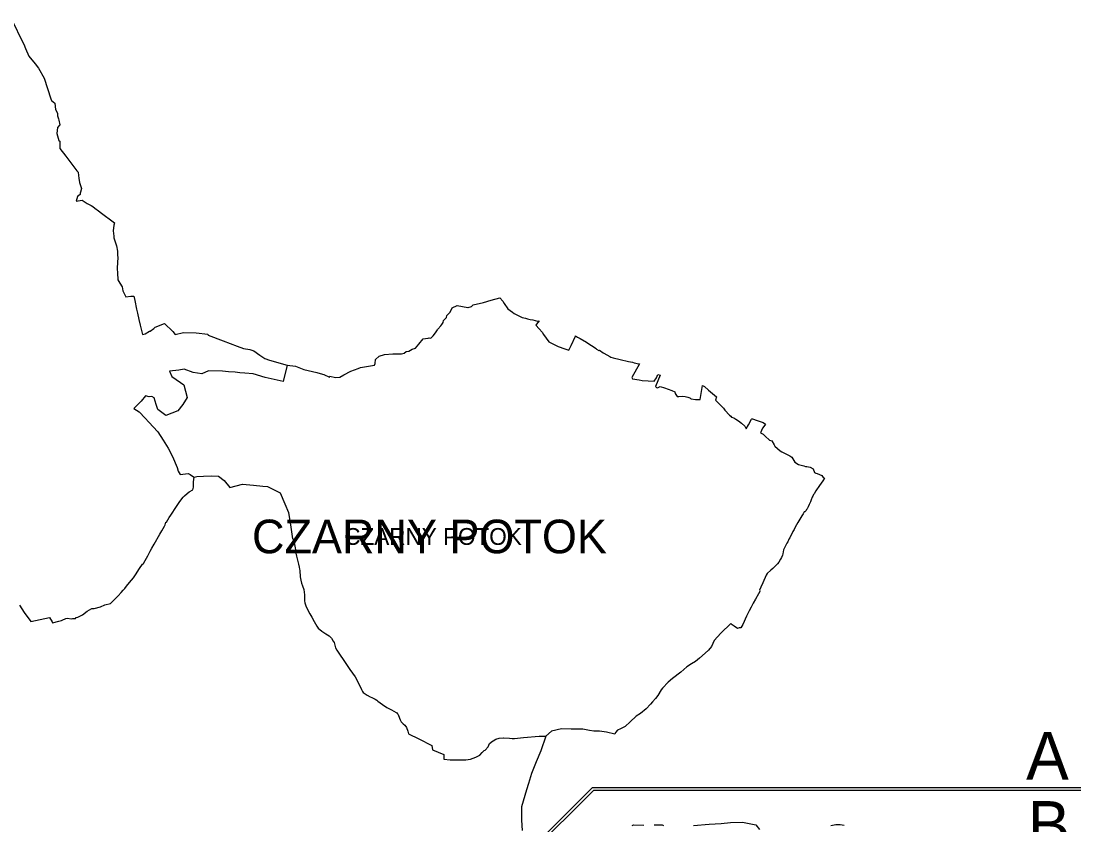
# Model space of a CAD drawing. Extents: x -562952 to -547638, y 190691 to 208158.
# Drawn here: x -557283 to -551614, y 202309 to 206612 of the extents above; entities that cross this region are included whole.
import ezdxf

# ---------------------------------------------------------------- set-up
doc = ezdxf.new("R2010")
doc.units = 0
for name, color, linetype in [('granica A_B', 7, 'Continuous'), ('granica_gminy', 7, 'Continuous'), ('granica_sołectwa', 7, 'Continuous'), ('nazwy miejscowości', 7, 'Continuous'), ('nazwy miejscowości DUŻE', 7, 'Continuous'), ('obwódka', 7, 'Continuous')]:
    doc.layers.add(name, color=color, linetype=linetype)

msp = doc.modelspace()

# ---------------------------------------------------------------- linework, layer by layer
at = {"layer": 'granica A_B'}
for points in [[(-554559.4, 202174.8), (-554225.8, 202508.4), (-551613.8, 202508.4)], [(-554557.2, 202157.2), (-554220, 202494.4), (-551613.8, 202494.4)]]:
    msp.add_lwpolyline(points, dxfattribs=at)
at = {"layer": 'granica_gminy'}
for points in [[(-557330.2, 206611.8), (-557277.5, 206504.5), (-557269.5, 206488.5), (-557259.1, 206466.4), (-557241.7, 206425), (-557208.3, 206383), (-557189.9, 206360.2), (-557159.5, 206306.4), (-557125.1, 206195.8), (-557120.8, 206186.2), (-557103.4, 206172.2), (-557100.1, 206139), (-557088, 206120), (-557088.7, 206105), (-557083.7, 206089.6), (-557080.7, 206081.2), (-557076, 206056.5), (-557089, 206043.3), (-557092.7, 206009.9), (-557081.4, 205973.4), (-557076, 205968.7), (-557075.7, 205929.6), (-557044.2, 205888.9), (-556985, 205810.3), (-556978.7, 205802.6), (-556976, 205785.3), (-556974.6, 205771.6), (-556971.3, 205748.1), (-556960.3, 205715.8), (-556965.7, 205696.4), (-556966.7, 205691.4), (-556967.3, 205684.3), (-556982.3, 205672.2), (-556988.7, 205648.3), (-556957.1, 205653.9), (-556929.1, 205636.3), (-556908.4, 205624.2), (-556899.5, 205619.8), (-556888.5, 205611.3), (-556870, 205596.1), (-556852.5, 205583.3), (-556831.1, 205567.6), (-556811.9, 205553.3), (-556784.1, 205532.5), (-556787.4, 205519.9), (-556791.3, 205489.2), (-556787.8, 205459.8), (-556786.7, 205451.4), (-556775.9, 205420.4), (-556773.7, 205408.4), (-556767.7, 205380.1), (-556767, 205358.3), (-556766.2, 205346.3), (-556769, 205290.3), (-556768, 205258.8), (-556765.9, 205233), (-556765.5, 205226.2), (-556755.2, 205209.9), (-556742.4, 205189.6), (-556739.1, 205167.3), (-556723.6, 205136.5), (-556696.6, 205138.8), (-556679.9, 205140.1), (-556675, 205115.6), (-556665.5, 205070.6), (-556660.4, 205048.5), (-556652.9, 205014.7), (-556646.6, 204984.5), (-556634.6, 204933.5), (-556619.9, 204937.6), (-556596.1, 204952.4), (-556592.3, 204952.4), (-556573.6, 204966.3), (-556566.7, 204973.4), (-556515.4, 204993.2), (-556472.2, 204950.4), (-556459.6, 204935), (-556414.7, 204945.6), (-556347.3, 204943.6), (-556284.8, 204936.3), (-556282.4, 204929.8), (-556201.9, 204900.2), (-556127.3, 204872), (-556093.3, 204859.7), (-556059.7, 204853), (-556038.7, 204846.7), (-556005.6, 204823.7), (-555978.5, 204805.4), (-555953.5, 204797), (-555859, 204770.3), (-555815.9, 204764.8), (-555771.3, 204746), (-555701.3, 204730.7), (-555683.9, 204725.4), (-555663.8, 204719.4), (-555634.2, 204706.5), (-555631.3, 204710.6), (-555601.8, 204703.6), (-555578.9, 204705.9), (-555557.5, 204718.5), (-555519.5, 204737.6), (-555479.6, 204752.5), (-555467.5, 204756.7), (-555456.4, 204758.9), (-555436.1, 204762), (-555391.7, 204769.5), (-555388.9, 204778.3), (-555386.4, 204800), (-555367.7, 204817.4), (-555339.8, 204826.7), (-555294.6, 204830), (-555247.3, 204829.9), (-555234.4, 204834.7), (-555222.7, 204843.7), (-555209.3, 204844.4), (-555190.3, 204855.1), (-555172.9, 204861.1), (-555155.7, 204882.4), (-555131.6, 204911.6), (-555108, 204914.9), (-555105.9, 204914.5), (-555100.8, 204916.2), (-555091.9, 204914.7), (-555079.2, 204926.3), (-555065.5, 204942.6), (-555055.5, 204959.8), (-555053.6, 204963.1), (-555038.4, 204981.1), (-555033, 204987.5), (-555026, 204998.8), (-555023.1, 205008.5), (-555007.3, 205025.3), (-555004.8, 205036.1), (-554988.6, 205054.2), (-554977.6, 205077.8), (-554950.7, 205088.8), (-554893.7, 205079.4), (-554891, 205079.3), (-554874.5, 205084.8), (-554865.2, 205092.6), (-554809.7, 205105.2), (-554769, 205118.6), (-554721.8, 205131), (-554706.8, 205113.4), (-554699.2, 205099.7), (-554679.3, 205071.5), (-554654.4, 205053.2), (-554644.9, 205046.4), (-554616.4, 205033), (-554603.2, 205025.4), (-554585.5, 205021.2), (-554573.2, 205018.3), (-554559, 205014.3), (-554545.1, 205012.3), (-554521, 205005.5), (-554511.3, 205008.1), (-554525.8, 204989.6), (-554529.8, 204984.9), (-554512.4, 204964.8), (-554495.9, 204946.8), (-554488.6, 204934.9), (-554459.4, 204894.2), (-554410.1, 204870.1), (-554375.1, 204858.2), (-554352.5, 204850.5), (-554339.7, 204875.4), (-554317.7, 204924.8), (-554316.9, 204926.8), (-554305.8, 204920.6), (-554291.7, 204912.4), (-554257.8, 204892.4), (-554245.8, 204884), (-554231.3, 204874.8), (-554205.9, 204859.1), (-554205.1, 204855.4), (-554192.4, 204848.6), (-554189.7, 204849.5), (-554169.9, 204836.5), (-554165, 204834), (-554134.1, 204815.5), (-554127.9, 204812.4), (-554116, 204809.2), (-554078.9, 204800.5), (-554033.4, 204789.5), (-554012.7, 204785.6), (-554002.6, 204782.9), (-553978, 204777.7), (-553974.5, 204776.5), (-554016.6, 204704.3), (-554012.2, 204697.5), (-554011.7, 204696.8), (-553976.2, 204691.6), (-553960.6, 204687.7), (-553895.6, 204685), (-553883.3, 204701.4), (-553876, 204720.7), (-553864.8, 204717.1), (-553889.9, 204656.4), (-553883.1, 204651.1), (-553878.7, 204647.9), (-553864.1, 204655), (-553841.1, 204647.9), (-553802.2, 204634.7), (-553785.1, 204626.9), (-553783.6, 204618.8), (-553772.6, 204602.4), (-553764.6, 204603.1), (-553742.5, 204604.1), (-553730, 204602.2), (-553716.8, 204598.8), (-553706, 204595.6), (-553701.9, 204591.4), (-553699.2, 204590.5), (-553674.5, 204585.3), (-553650.5, 204586.8), (-553637.6, 204660.7), (-553627.9, 204655.5), (-553606, 204636.3), (-553563.6, 204600.2), (-553567.6, 204581.9), (-553555, 204570.6), (-553536.4, 204551.1), (-553524.9, 204539.2), (-553518.2, 204529.4), (-553493, 204502.8), (-553487, 204496.3), (-553482, 204492.2), (-553469.7, 204487.8), (-553460, 204481.5), (-553445, 204471.4), (-553429.5, 204459.1), (-553411.2, 204444), (-553404.7, 204429.6), (-553392.4, 204451.1), (-553376.3, 204481), (-553373.3, 204482.8), (-553369.8, 204482.5), (-553344.7, 204473.8), (-553313.9, 204463.3), (-553300.9, 204453.2), (-553309.2, 204441.7), (-553316.1, 204432.1), (-553327.8, 204407.6), (-553312.5, 204399.7), (-553301.7, 204389.6), (-553280.1, 204369.2), (-553267.6, 204364.7), (-553255, 204343.4), (-553250.9, 204336.6), (-553221.8, 204311.7), (-553212.8, 204306.5), (-553187.6, 204292.6), (-553171.4, 204284.3), (-553159.3, 204277.8), (-553143.1, 204249.9), (-553124.6, 204238.5), (-553096.5, 204231.3), (-553086.4, 204227.8), (-553079.6, 204227), (-553061.2, 204224.5), (-553045.5, 204215.4), (-553037.9, 204195.2), (-553031.2, 204191.4), (-553023.7, 204189.6), (-552999.9, 204179.7), (-552992.7, 204168.5), (-552985.3, 204164.4), (-552994.5, 204150.9), (-553002.9, 204138.2), (-553011.7, 204125.6), (-553031.4, 204096.4), (-553040.9, 204081.3), (-553043.4, 204077.2), (-553047.5, 204069), (-553050.6, 204062.9), (-553057.2, 204048.2), (-553058.6, 204044.1), (-553060.8, 204039.1), (-553067.1, 204024.3), (-553072.9, 204011.8), (-553078.3, 204001.5), (-553080.8, 203997.2), (-553083.8, 203991.5), (-553087.5, 203987.5), (-553090.4, 203985.5), (-553094.1, 203983.9), (-553099.5, 203974.6), (-553105.7, 203963.3), (-553116.9, 203945.3), (-553127.9, 203926.7), (-553141.9, 203902.9), (-553148.2, 203890.6), (-553154.1, 203879.1), (-553155.7, 203875.1), (-553171.1, 203845.7), (-553175.7, 203837.6), (-553182, 203824.7), (-553186.5, 203816.3), (-553204, 203781.6), (-553204.6, 203780.4), (-553207.9, 203759.9), (-553210.4, 203753.4), (-553215.7, 203740.5), (-553219.7, 203730.9), (-553229.1, 203714.5), (-553236.2, 203706.8), (-553249.6, 203693.5), (-553262, 203680.6), (-553271.8, 203672.4), (-553291.2, 203654.5), (-553296.8, 203646.3), (-553315.8, 203604.2), (-553325.4, 203581.5), (-553332.1, 203564.6), (-553330.8, 203562.5), (-553331.3, 203558.1), (-553338.5, 203545.9), (-553354.2, 203516.3), (-553365.9, 203495.3), (-553377.4, 203474.9), (-553388.5, 203454.7), (-553399.3, 203432.9), (-553402.2, 203426.7), (-553422.8, 203380.8), (-553432, 203364.4), (-553441.3, 203363.8), (-553450.9, 203359.9), (-553469.1, 203373.1), (-553478.3, 203380.5), (-553487, 203386.5), (-553540.4, 203334.9), (-553574.7, 203296.1), (-553590.3, 203263.2), (-553605.2, 203244.1), (-553622.8, 203227.2), (-553653, 203201.3), (-553675.5, 203182.9), (-553697.1, 203171), (-553721.7, 203154.7), (-553754.2, 203127.1), (-553797.7, 203092.9), (-553821.3, 203072), (-553851, 203040.9), (-553859.3, 203031), (-553876.1, 203001), (-553889.1, 202985), (-553905.6, 202968.2), (-553915.3, 202954.7), (-553939.1, 202930.4), (-553969.6, 202904.7), (-553992.4, 202890.9), (-554025.3, 202860), (-554051.2, 202835.6), (-554076.6, 202822.3), (-554091.7, 202815.3), (-554103.6, 202802.6), (-554106.9, 202795), (-554151.9, 202805.8), (-554188.7, 202810.2), (-554218.8, 202811), (-554242, 202814.5), (-554277.7, 202820.2), (-554297.8, 202821.5), (-554339.6, 202820.5), (-554392.4, 202823.1), (-554445.8, 202810.5), (-554476.4, 202783.6), (-554502.2, 202705.9), (-554527.1, 202645.7), (-554552.1, 202583.8), (-554569.4, 202529.3), (-554579.5, 202496), (-554588.2, 202466.6), (-554605.7, 202405.1), (-554607, 202333.1), (-554602.3, 202278.1)], [(-554013.3, 202305), (-554007.8, 202308.9), (-553951.8, 202307.6)], [(-553896.2, 202308.1), (-553852.8, 202308.9), (-553847.1, 202305)], [(-553686.5, 202306), (-553602.2, 202312), (-553538, 202316.6), (-553487.2, 202321), (-553423.4, 202323.8), (-553352.3, 202309.4), (-553333.1, 202284.1)], [(-552950.9, 202305), (-552923.6, 202310.7), (-552900.6, 202310.9), (-552880.3, 202307.6)]]:
    msp.add_lwpolyline(points, dxfattribs=at)
at = {"layer": 'granica_sołectwa'}
for points in [[(-555860, 204770.6), (-555882.1, 204682.5), (-555977.9, 204704.1), (-556041.9, 204724.3), (-556086.4, 204727.7), (-556113.4, 204729.7), (-556138.7, 204732.4), (-556173.2, 204734.4), (-556206.6, 204738.5), (-556281.1, 204739.5), (-556316.1, 204723.3), (-556363.1, 204730), (-556410, 204748.3), (-556439.5, 204742.7), (-556489.8, 204737.5), (-556476, 204709.2), (-556453.6, 204692.8), (-556430.5, 204676.7), (-556412.3, 204664.8), (-556394.8, 204596.4), (-556417.5, 204559.1), (-556444, 204524.8), (-556509.2, 204500.2), (-556551.1, 204533.4), (-556560.8, 204558.7), (-556570.5, 204594.9), (-556583.2, 204601.6), (-556598.4, 204601.2), (-556618.2, 204606.1), (-556641.7, 204576.6), (-556679.3, 204537.1), (-556651.3, 204519.7), (-556620, 204486.2), (-556600.2, 204464.9), (-556552.2, 204412.9), (-556523.5, 204367.8), (-556497, 204324.9), (-556474, 204280.3), (-556449, 204222.5), (-556442.3, 204202.2), (-556431.5, 204184.3), (-556388.7, 204189.5), (-556378.6, 204185), (-556356.4, 204169)], [(-556361.1, 204116), (-556361.1, 204126.8), (-556361.5, 204145.3), (-556357.1, 204170.5), (-556343.1, 204174.3), (-556306.9, 204176.3), (-556265.1, 204178.2), (-556228, 204175.2), (-556197.3, 204152.3), (-556166.2, 204114.1), (-556099.1, 204132.3), (-556040.1, 204126.9), (-555990.3, 204122.3), (-555965.7, 204119.8), (-555897.2, 204085.9), (-555872.3, 204027.1), (-555851.9, 203982), (-555839.6, 203902.7), (-555838.5, 203890.2), (-555831.5, 203840.5), (-555826.7, 203838.7), (-555819.4, 203801.4), (-555814, 203772.1), (-555812.6, 203762.9), (-555810.1, 203747.2), (-555803.5, 203719.5), (-555799.2, 203704.8), (-555795.1, 203687.6), (-555793.1, 203677.3), (-555791.8, 203670.3), (-555789.9, 203636.3), (-555787.2, 203618.1), (-555783.6, 203602.7), (-555778.2, 203587.7), (-555771.4, 203568.2), (-555768.6, 203553.8), (-555767.4, 203540.4), (-555766.4, 203517.6), (-555767.1, 203508.2), (-555765, 203497.3), (-555760.4, 203482.1), (-555751.5, 203462), (-555738.3, 203439), (-555727, 203420.4), (-555715.4, 203397), (-555701.1, 203371.9), (-555693.7, 203362.6), (-555674.8, 203346.2), (-555652.5, 203331.1), (-555634.8, 203320.2), (-555622.4, 203308.4), (-555613.2, 203292.3), (-555609.2, 203285), (-555600.6, 203257.3), (-555594.9, 203244.6), (-555541.5, 203167.2)], [(-557291.4, 203484.1), (-557267.3, 203446.2), (-557230.6, 203398.3), (-557130.8, 203418.8), (-557116.6, 203395.3), (-557115.9, 203390.4), (-557081, 203399), (-557068, 203402.5), (-557063.9, 203405.5), (-557044.8, 203413.3), (-557035.5, 203415.1), (-557015.1, 203412.2), (-557007.5, 203412.8), (-556992.6, 203414), (-556987.9, 203419.1), (-556979.6, 203421.4), (-556955.1, 203434), (-556930.5, 203453.6), (-556904.9, 203466.8), (-556893.1, 203466.8), (-556858.8, 203476.6), (-556835.1, 203487), (-556805.5, 203494.3), (-556764.5, 203535.2), (-556747.8, 203552.7), (-556736.5, 203565.4), (-556728.9, 203574.5), (-556719.6, 203586), (-556703.1, 203606.1), (-556682, 203632), (-556671.7, 203646.6), (-556649.4, 203680.6), (-556633.4, 203704), (-556628.6, 203708.8), (-556620.2, 203724.9), (-556605.8, 203748.9), (-556592.2, 203773.7), (-556583.3, 203789.3), (-556570.6, 203811.3), (-556540.6, 203865.1), (-556530.1, 203883), (-556516.4, 203907.5), (-556512.8, 203915.4), (-556508.8, 203928.8), (-556505.1, 203928.5), (-556491.1, 203954.2), (-556482.5, 203967.1), (-556451.6, 204014), (-556433.6, 204039.6), (-556416.5, 204063.3), (-556409.2, 204070.2), (-556395.5, 204082.8), (-556384.1, 204091.5), (-556364.1, 204102.4), (-556361.1, 204116)], [(-555541.5, 203167.2), (-555524, 203141.1), (-555496.8, 203101.6), (-555483.1, 203078.6), (-555463, 203033.6), (-555457.3, 203022.4), (-555454.1, 203018), (-555431.9, 203003.8), (-555415.2, 202993.5), (-555406.3, 202991.1), (-555388.8, 202982.2), (-555380.2, 202976.1), (-555374.9, 202971.5), (-555350.5, 202953.4), (-555326.3, 202937.5), (-555319.7, 202933.4), (-555301.1, 202924.1), (-555276.5, 202910.6), (-555273.2, 202908.4), (-555268.8, 202903.7), (-555266.4, 202899.1), (-555259.5, 202879.8), (-555256, 202871.3), (-555249.9, 202859.8), (-555246.9, 202857.2), (-555238.6, 202849.3), (-555229.8, 202841.6), (-555222.2, 202829.4), (-555215, 202810.7), (-555209.8, 202796.8), (-555156.2, 202769.2), (-555085.3, 202733.8), (-555082.4, 202710.8), (-555021, 202684.6), (-555021.6, 202661), (-554987.6, 202657.6), (-554949.3, 202656.5), (-554904.8, 202656.9), (-554878.2, 202659.8), (-554849.7, 202671.5), (-554829.4, 202681.5), (-554815.8, 202696), (-554809.6, 202703.4), (-554805.4, 202706.4), (-554800.8, 202708.8), (-554784.3, 202725.9), (-554776.9, 202744.8), (-554761.3, 202756.6), (-554757, 202759.2), (-554743, 202767.4), (-554726.3, 202772.6), (-554703.5, 202775.3), (-554703, 202774.3), (-554669.7, 202772.6), (-554656.3, 202771.7)], [(-554656.3, 202771.7), (-554642.9, 202771.3), (-554596.3, 202776.7), (-554511.2, 202784.4), (-554476.4, 202783.6)]]:
    msp.add_lwpolyline(points, dxfattribs=at)
at = {"layer": 'obwódka'}
for points in [[(-557330.2, 206611.8), (-557277.5, 206504.5), (-557269.5, 206488.5), (-557259.1, 206466.4), (-557241.7, 206425), (-557208.3, 206383), (-557189.9, 206360.2), (-557159.5, 206306.4), (-557125.1, 206195.8), (-557120.8, 206186.2), (-557103.4, 206172.2), (-557100.1, 206139), (-557088, 206120), (-557088.7, 206105), (-557083.7, 206089.6), (-557080.7, 206081.2), (-557076, 206056.5), (-557089, 206043.3), (-557092.7, 206009.9), (-557081.4, 205973.4), (-557076, 205968.7), (-557075.7, 205929.6), (-557044.2, 205888.9), (-556985, 205810.3), (-556978.7, 205802.6), (-556976, 205785.3), (-556974.6, 205771.6), (-556971.3, 205748.1), (-556960.3, 205715.8), (-556965.7, 205696.4), (-556966.7, 205691.4), (-556967.3, 205684.3), (-556982.3, 205672.2), (-556988.7, 205648.3), (-556957.1, 205653.9), (-556929.1, 205636.3), (-556908.4, 205624.2), (-556899.5, 205619.8), (-556888.5, 205611.3), (-556870, 205596.1), (-556852.5, 205583.3), (-556831.1, 205567.6), (-556811.9, 205553.3), (-556784.1, 205532.5), (-556787.4, 205519.9), (-556791.3, 205489.2), (-556787.8, 205459.8), (-556786.7, 205451.4), (-556775.9, 205420.4), (-556773.7, 205408.4), (-556767.7, 205380.1), (-556767, 205358.3), (-556766.2, 205346.3), (-556769, 205290.3), (-556768, 205258.8), (-556765.9, 205233), (-556765.5, 205226.2), (-556755.2, 205209.9), (-556742.4, 205189.6), (-556739.1, 205167.3), (-556723.6, 205136.5), (-556696.6, 205138.8), (-556679.9, 205140.1), (-556675, 205115.6), (-556665.5, 205070.6), (-556660.4, 205048.5), (-556652.9, 205014.7), (-556646.6, 204984.5), (-556634.6, 204933.5), (-556619.9, 204937.6), (-556596.1, 204952.4), (-556592.3, 204952.4), (-556573.6, 204966.3), (-556566.7, 204973.4), (-556515.4, 204993.2), (-556472.2, 204950.4), (-556459.6, 204935), (-556414.7, 204945.6), (-556347.3, 204943.6), (-556284.8, 204936.3), (-556282.4, 204929.8), (-556201.9, 204900.2), (-556127.3, 204872), (-556093.3, 204859.7), (-556059.7, 204853), (-556038.7, 204846.7), (-556005.6, 204823.7), (-555978.5, 204805.4), (-555953.5, 204797), (-555859, 204770.3), (-555815.9, 204764.8), (-555771.3, 204746), (-555701.3, 204730.7), (-555683.9, 204725.4), (-555663.8, 204719.4), (-555634.2, 204706.5), (-555631.3, 204710.6), (-555601.8, 204703.6), (-555578.9, 204705.9), (-555557.5, 204718.5), (-555519.5, 204737.6), (-555479.6, 204752.5), (-555467.5, 204756.7), (-555456.4, 204758.9), (-555436.1, 204762), (-555391.7, 204769.5), (-555388.9, 204778.3), (-555386.4, 204800), (-555367.7, 204817.4), (-555339.8, 204826.7), (-555294.6, 204830), (-555247.3, 204829.9), (-555234.4, 204834.7), (-555222.7, 204843.7), (-555209.3, 204844.4), (-555190.3, 204855.1), (-555172.9, 204861.1), (-555155.7, 204882.4), (-555131.6, 204911.6), (-555108, 204914.9), (-555105.9, 204914.5), (-555100.8, 204916.2), (-555091.9, 204914.7), (-555079.2, 204926.3), (-555065.5, 204942.6), (-555055.5, 204959.8), (-555053.6, 204963.1), (-555038.4, 204981.1), (-555033, 204987.5), (-555026, 204998.8), (-555023.1, 205008.5), (-555007.3, 205025.3), (-555004.8, 205036.1), (-554988.6, 205054.2), (-554977.6, 205077.8), (-554950.7, 205088.8), (-554893.7, 205079.4), (-554891, 205079.3), (-554874.5, 205084.8), (-554865.2, 205092.6), (-554809.7, 205105.2), (-554769, 205118.6), (-554721.8, 205131), (-554706.8, 205113.4), (-554699.2, 205099.7), (-554679.3, 205071.5), (-554654.4, 205053.2), (-554644.9, 205046.4), (-554616.4, 205033), (-554603.2, 205025.4), (-554585.5, 205021.2), (-554573.2, 205018.3), (-554559, 205014.3), (-554545.1, 205012.3), (-554521, 205005.5), (-554511.3, 205008.1), (-554525.8, 204989.6), (-554529.8, 204984.9), (-554512.4, 204964.8), (-554495.9, 204946.8), (-554488.6, 204934.9), (-554459.4, 204894.2), (-554410.1, 204870.1), (-554375.1, 204858.2), (-554352.5, 204850.5), (-554339.7, 204875.4), (-554317.7, 204924.8), (-554316.9, 204926.8), (-554305.8, 204920.6), (-554291.7, 204912.4), (-554257.8, 204892.4), (-554245.8, 204884), (-554231.3, 204874.8), (-554205.9, 204859.1), (-554205.1, 204855.4), (-554192.4, 204848.6), (-554189.7, 204849.5), (-554169.9, 204836.5), (-554165, 204834), (-554134.1, 204815.5), (-554127.9, 204812.4), (-554116, 204809.2), (-554078.9, 204800.5), (-554033.4, 204789.5), (-554012.7, 204785.6), (-554002.6, 204782.9), (-553978, 204777.7), (-553974.5, 204776.5), (-554016.6, 204704.3), (-554012.2, 204697.5), (-554011.7, 204696.8), (-553976.2, 204691.6), (-553960.6, 204687.7), (-553895.6, 204685), (-553883.3, 204701.4), (-553876, 204720.7), (-553864.8, 204717.1), (-553889.9, 204656.4), (-553883.1, 204651.1), (-553878.7, 204647.9), (-553864.1, 204655), (-553841.1, 204647.9), (-553802.2, 204634.7), (-553785.1, 204626.9), (-553783.6, 204618.8), (-553772.6, 204602.4), (-553764.6, 204603.1), (-553742.5, 204604.1), (-553730, 204602.2), (-553716.8, 204598.8), (-553706, 204595.6), (-553701.9, 204591.4), (-553699.2, 204590.5), (-553674.5, 204585.3), (-553650.5, 204586.8), (-553637.6, 204660.7), (-553627.9, 204655.5), (-553606, 204636.3), (-553563.6, 204600.2), (-553567.6, 204581.9), (-553555, 204570.6), (-553536.4, 204551.1), (-553524.9, 204539.2), (-553518.2, 204529.4), (-553493, 204502.8), (-553487, 204496.3), (-553482, 204492.2), (-553469.7, 204487.8), (-553460, 204481.5), (-553445, 204471.4), (-553429.5, 204459.1), (-553411.2, 204444), (-553404.7, 204429.6), (-553392.4, 204451.1), (-553376.3, 204481), (-553373.3, 204482.8), (-553369.8, 204482.5), (-553344.7, 204473.8), (-553313.9, 204463.3), (-553300.9, 204453.2), (-553309.2, 204441.7), (-553316.1, 204432.1), (-553327.8, 204407.6), (-553312.5, 204399.7), (-553301.7, 204389.6), (-553280.1, 204369.2), (-553267.6, 204364.7), (-553255, 204343.4), (-553250.9, 204336.6), (-553221.8, 204311.7), (-553212.8, 204306.5), (-553187.6, 204292.6), (-553171.4, 204284.3), (-553159.3, 204277.8), (-553143.1, 204249.9), (-553124.6, 204238.5), (-553096.5, 204231.3), (-553086.4, 204227.8), (-553079.6, 204227), (-553061.2, 204224.5), (-553045.5, 204215.4), (-553037.9, 204195.2), (-553031.2, 204191.4), (-553023.7, 204189.6), (-552999.9, 204179.7), (-552992.7, 204168.5), (-552985.3, 204164.4), (-552994.5, 204150.9), (-553002.9, 204138.2), (-553011.7, 204125.6), (-553031.4, 204096.4), (-553040.9, 204081.3), (-553043.4, 204077.2), (-553047.5, 204069), (-553050.6, 204062.9), (-553057.2, 204048.2), (-553058.6, 204044.1), (-553060.8, 204039.1), (-553067.1, 204024.3), (-553072.9, 204011.8), (-553078.3, 204001.5), (-553080.8, 203997.2), (-553083.8, 203991.5), (-553087.5, 203987.5), (-553090.4, 203985.5), (-553094.1, 203983.9), (-553099.5, 203974.6), (-553105.7, 203963.3), (-553116.9, 203945.3), (-553127.9, 203926.7), (-553141.9, 203902.9), (-553148.2, 203890.6), (-553154.1, 203879.1), (-553155.7, 203875.1), (-553171.1, 203845.7), (-553175.7, 203837.6), (-553182, 203824.7), (-553186.5, 203816.3), (-553204, 203781.6), (-553204.6, 203780.4), (-553207.9, 203759.9), (-553210.4, 203753.4), (-553215.7, 203740.5), (-553219.7, 203730.9), (-553229.1, 203714.5), (-553236.2, 203706.8), (-553249.6, 203693.5), (-553262, 203680.6), (-553271.8, 203672.4), (-553291.2, 203654.5), (-553296.8, 203646.3), (-553315.8, 203604.2), (-553325.4, 203581.5), (-553332.1, 203564.6), (-553330.8, 203562.5), (-553331.3, 203558.1), (-553338.5, 203545.9), (-553354.2, 203516.3), (-553365.9, 203495.3), (-553377.4, 203474.9), (-553388.5, 203454.7), (-553399.3, 203432.9), (-553402.2, 203426.7), (-553422.8, 203380.8), (-553432, 203364.4), (-553441.3, 203363.8), (-553450.9, 203359.9), (-553469.1, 203373.1), (-553478.3, 203380.5), (-553487, 203386.5), (-553540.4, 203334.9), (-553574.7, 203296.1), (-553590.3, 203263.2), (-553605.2, 203244.1), (-553622.8, 203227.2), (-553653, 203201.3), (-553675.5, 203182.9), (-553697.1, 203171), (-553721.7, 203154.7), (-553754.2, 203127.1), (-553797.7, 203092.9), (-553821.3, 203072), (-553851, 203040.9), (-553859.3, 203031), (-553876.1, 203001), (-553889.1, 202985), (-553905.6, 202968.2), (-553915.3, 202954.7), (-553939.1, 202930.4), (-553969.6, 202904.7), (-553992.4, 202890.9), (-554025.3, 202860), (-554051.2, 202835.6), (-554076.6, 202822.3), (-554091.7, 202815.3), (-554103.6, 202802.6), (-554106.9, 202795), (-554151.9, 202805.8), (-554188.7, 202810.2), (-554218.8, 202811), (-554242, 202814.5), (-554277.7, 202820.2), (-554297.8, 202821.5), (-554339.6, 202820.5), (-554392.4, 202823.1), (-554445.8, 202810.5), (-554476.4, 202783.6), (-554502.2, 202705.9), (-554527.1, 202645.7), (-554552.1, 202583.8), (-554569.4, 202529.3), (-554579.5, 202496), (-554588.2, 202466.6), (-554605.7, 202405.1), (-554607, 202333.1), (-554602.3, 202278.1)], [(-554013.3, 202305), (-554007.8, 202308.9), (-553951.8, 202307.6)], [(-553896.2, 202308.1), (-553852.8, 202308.9), (-553847.1, 202305)], [(-553686.5, 202306), (-553602.2, 202312), (-553538, 202316.6), (-553487.2, 202321), (-553423.4, 202323.8), (-553352.3, 202309.4), (-553333.1, 202284.1)], [(-552950.9, 202305), (-552923.6, 202310.7), (-552900.6, 202310.9), (-552880.3, 202307.6)]]:
    msp.add_lwpolyline(points, dxfattribs=at)

# ---------------------------------------------------------------- texts
at = {"layer": 'granica A_B'}
for s, p in [('A', (-551906.5, 202550.5)), ('B', (-551898.4, 202179.9))]:
    msp.add_text(s, height=256, rotation=360, dxfattribs=at).set_placement(p)
at = {"layer": 'nazwy miejscowości'}
msp.add_text('CZARNY POTOK', height=90, dxfattribs=at).set_placement((-555554.3, 203807.8))
at = {"layer": 'nazwy miejscowości DUŻE'}
msp.add_text('CZARNY POTOK', height=180, dxfattribs=at).set_placement((-556048.1, 203762.8))

doc.saveas('drawing.dxf')
